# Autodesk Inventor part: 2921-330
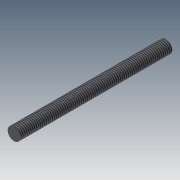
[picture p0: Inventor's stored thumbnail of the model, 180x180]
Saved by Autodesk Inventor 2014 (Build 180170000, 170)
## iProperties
Company: NHTSA/VRTC
Created: 2012-08
Part Number: 2921-330
Material: Steel
Document SubType Name: Modeling
Designer: Mike Vanvoorhis
Density: 7.85 g/cm^3
Mass: 151.549 g
Surface Area: 63.3384 cm^2
Volume: 19.3056 cm^3
Project: CHILD SIDE IMPACT SLED
Description: D-RING LOWER ANCHOR THREADED ROD
Stock Number: ROD, THREADED 1/2-13 x 6" (152.4 mm) LG.
Appearance: Steel
DESIGN DATE: 2012-11-05
Author: Dave Walker
Title: D-Ring Lower Anchor Threaded Rod
Subject: Child Side Impact Sled
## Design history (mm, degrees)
sketch "Sketch1"
  geometry: C1 r 6.35 at (0, 0); 1 further point
  constraints: 1 centre point, 1 coincident
  dimensions: "d0" = 12.7 diameter of C1
extrude "Extrusion1" new body sketch "Sketch1" distance "d1" = 152.4; taper "d2" = 0 deg
thread "Thread1" dims "d3" = 25.4, "d4" = 0
body "Solid1"
